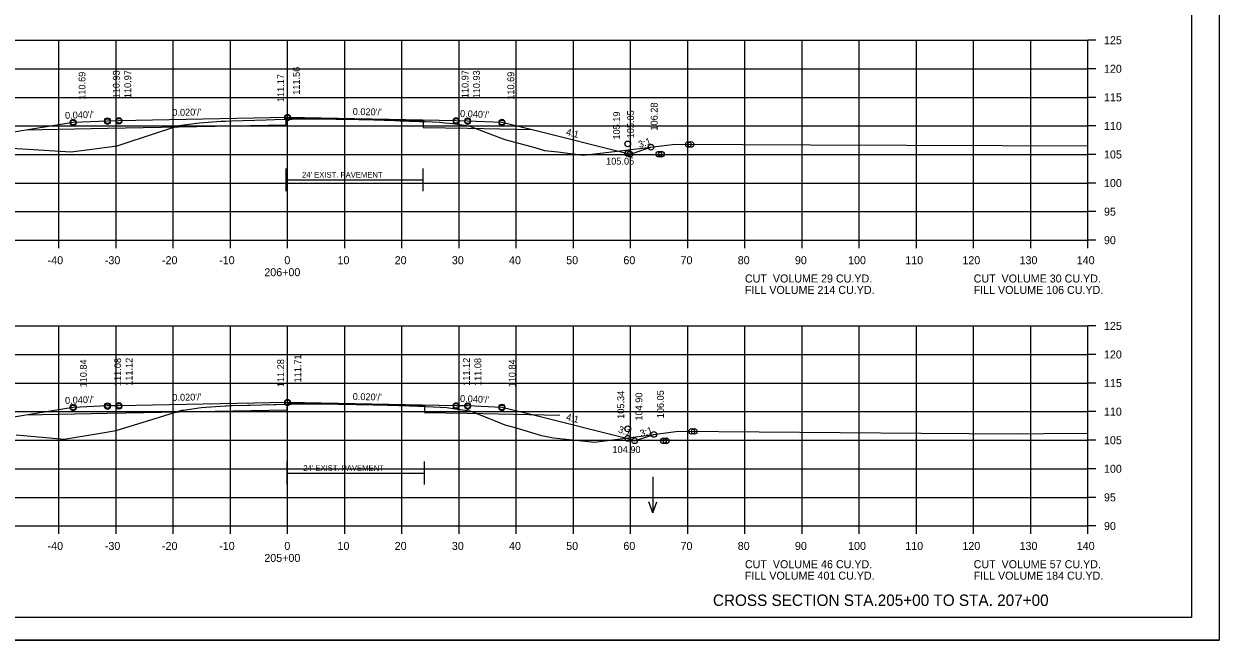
# Model space of a CAD drawing. Extents: x 1175611 to 1176402, y -433344 to -416213.
# Drawn here: x 1175734.9 to 1175943.9, y -425023.4 to -424915.5 of the extents above; entities that cross this region are included whole.
import ezdxf

# ---------------------------------------------------------------- set-up
doc = ezdxf.new("R2010")
doc.units = 0
for name, color, linetype in [('Default', 7, 'Continuous'), ('R_Alt Surface', 7, 'Continuous'), ('R_Axis', 7, 'Continuous'), ('R_Axis Annot', 7, 'Continuous'), ('R_Border', 7, 'Continuous'), ('R_Draft', 7, 'Continuous'), ('R_Exist Surface', 7, 'Continuous'), ('R_Fin Surface', 7, 'Continuous'), ('R_Grid', 7, 'Continuous'), ('R_No Plot', 7, 'Continuous'), ('R_Water Annot', 7, 'Continuous'), ('R_Xsect Elev', 7, 'Continuous'), ('R_Xsect Slope', 7, 'Continuous')]:
    doc.layers.add(name, color=color, linetype=linetype)

msp = doc.modelspace()

# ---------------------------------------------------------------- linework, layer by layer
at = {"layer": 'R_Alt Surface'}
for p, q in [((1175780.7, -424942.81), (1175804.7, -424942.81)), ((1175780.91, -424994.12), (1175804.91, -424994.12))]:
    msp.add_line(p, q, dxfattribs=at)
for points in [[(1175735.2, -424934.07), (1175749.47, -424933.78), (1175780.7, -424933.16), (1175780.7, -424931.98), (1175780.97, -424931.98), (1175804.7, -424932.46), (1175804.7, -424933.63), (1175812.47, -424933.78), (1175823.75, -424934.01)], [(1175780.7, -424944.81), (1175780.7, -424940.81)], [(1175804.7, -424944.81), (1175804.7, -424940.81)], [(1175735.2, -424983.94), (1175749.47, -424983.65), (1175780.91, -424983.03), (1175780.97, -424981.86), (1175780.97, -424981.86), (1175804.91, -424982.34), (1175804.91, -424983.5), (1175812.47, -424983.65), (1175828.57, -424983.98)], [(1175780.91, -424996.12), (1175780.91, -424992.12)], [(1175804.91, -424996.12), (1175804.91, -424992.12)]]:
    msp.add_lwpolyline(points, dxfattribs=at)
at = {"layer": 'R_Axis'}
for p, q in [((1175920.97, -424953.37), (1175920.97, -424918.37)), ((1175922.37, -424918.37), (1175920.97, -424918.37)), ((1175922.37, -424923.37), (1175920.97, -424923.37)), ((1175922.37, -424928.37), (1175920.97, -424928.37)), ((1175922.37, -424933.37), (1175920.97, -424933.37)), ((1175922.37, -424938.37), (1175920.97, -424938.37)), ((1175922.37, -424943.37), (1175920.97, -424943.37)), ((1175922.37, -424948.37), (1175920.97, -424948.37)), ((1175640.97, -424953.37), (1175920.97, -424953.37)), ((1175740.97, -424954.77), (1175740.97, -424953.37)), ((1175750.97, -424954.77), (1175750.97, -424953.37)), ((1175760.97, -424954.77), (1175760.97, -424953.37)), ((1175770.97, -424954.77), (1175770.97, -424953.37)), ((1175780.97, -424954.77), (1175780.97, -424953.37)), ((1175790.97, -424954.77), (1175790.97, -424953.37)), ((1175800.97, -424954.77), (1175800.97, -424953.37)), ((1175810.97, -424954.77), (1175810.97, -424953.37)), ((1175820.97, -424954.77), (1175820.97, -424953.37)), ((1175830.97, -424954.77), (1175830.97, -424953.37)), ((1175840.97, -424954.77), (1175840.97, -424953.37)), ((1175850.97, -424954.77), (1175850.97, -424953.37)), ((1175860.97, -424954.77), (1175860.97, -424953.37)), ((1175870.97, -424954.77), (1175870.97, -424953.37)), ((1175880.97, -424954.77), (1175880.97, -424953.37)), ((1175890.97, -424954.77), (1175890.97, -424953.37)), ((1175900.97, -424954.77), (1175900.97, -424953.37)), ((1175910.97, -424954.77), (1175910.97, -424953.37)), ((1175920.97, -424954.77), (1175920.97, -424953.37)), ((1175922.37, -424953.37), (1175920.97, -424953.37)), ((1175920.97, -425003.37), (1175920.97, -424968.37)), ((1175922.37, -424968.37), (1175920.97, -424968.37)), ((1175922.37, -424973.37), (1175920.97, -424973.37)), ((1175922.37, -424978.37), (1175920.97, -424978.37)), ((1175922.37, -424983.37), (1175920.97, -424983.37)), ((1175922.37, -424988.37), (1175920.97, -424988.37)), ((1175922.37, -424993.37), (1175920.97, -424993.37)), ((1175922.37, -424998.37), (1175920.97, -424998.37)), ((1175640.97, -425003.37), (1175920.97, -425003.37)), ((1175740.97, -425004.77), (1175740.97, -425003.37)), ((1175750.97, -425004.77), (1175750.97, -425003.37)), ((1175760.97, -425004.77), (1175760.97, -425003.37)), ((1175770.97, -425004.77), (1175770.97, -425003.37)), ((1175780.97, -425004.77), (1175780.97, -425003.37)), ((1175790.97, -425004.77), (1175790.97, -425003.37)), ((1175800.97, -425004.77), (1175800.97, -425003.37)), ((1175810.97, -425004.77), (1175810.97, -425003.37)), ((1175820.97, -425004.77), (1175820.97, -425003.37)), ((1175830.97, -425004.77), (1175830.97, -425003.37)), ((1175840.97, -425004.77), (1175840.97, -425003.37)), ((1175850.97, -425004.77), (1175850.97, -425003.37)), ((1175860.97, -425004.77), (1175860.97, -425003.37)), ((1175870.97, -425004.77), (1175870.97, -425003.37)), ((1175880.97, -425004.77), (1175880.97, -425003.37)), ((1175890.97, -425004.77), (1175890.97, -425003.37)), ((1175900.97, -425004.77), (1175900.97, -425003.37)), ((1175910.97, -425004.77), (1175910.97, -425003.37)), ((1175920.97, -425004.77), (1175920.97, -425003.37)), ((1175922.37, -425003.37), (1175920.97, -425003.37))]:
    msp.add_line(p, q, dxfattribs=at)
at = {"layer": 'R_Border'}
for q in [(1175939.15, -424813.91), (1175622.97, -425019.37)]:
    msp.add_line((1175939.15, -425019.37), q, dxfattribs=at)
at = {"layer": 'R_Exist Surface'}
for points in [[(1175728.05, -424936.95), (1175743.05, -424937.92), (1175745.85, -424937.56), (1175751.19, -424936.85), (1175758.24, -424934.54), (1175762.03, -424933.3), (1175762.82, -424933.18), (1175765.57, -424932.81), (1175769.35, -424932.56), (1175769.97, -424932.51), (1175770.01, -424932.51), (1175770.03, -424932.51), (1175771.21, -424932.47), (1175777.23, -424932.28), (1175778.66, -424932.25), (1175781.45, -424932.18), (1175781.77, -424932.18), (1175782.98, -424932.15), (1175784.22, -424932.15), (1175788.23, -424932.13), (1175789.42, -424932.16), (1175793.43, -424932.25), (1175794.21, -424932.27), (1175799.75, -424932.43), (1175800.67, -424932.46), (1175804.07, -424932.58), (1175805.05, -424932.62), (1175806.24, -424932.68), (1175807.57, -424932.74), (1175808.47, -424932.8), (1175809.22, -424932.89), (1175810.29, -424933.03), (1175812.7, -424933.35), (1175816.37, -424934.78), (1175818.97, -424935.73), (1175824.2, -424937.17), (1175825.9, -424937.66), (1175828.25, -424937.93), (1175832.7, -424938.47), (1175839.16, -424937.74), (1175848.75, -424936.59), (1175872.46, -424936.69), (1175905.97, -424936.8), (1175920.97, -424936.84)], [(1175733.48, -424987.44), (1175741.88, -424988.2), (1175747.93, -424987.17), (1175751, -424986.67), (1175759.48, -424984.07), (1175762.47, -424983.14), (1175762.79, -424983.1), (1175765.84, -424982.67), (1175770.03, -424982.37), (1175770.26, -424982.35), (1175770.32, -424982.35), (1175771, -424982.31), (1175771.29, -424982.31), (1175773.98, -424982.24), (1175774.46, -424982.23), (1175778.58, -424982.13), (1175778.94, -424982.12), (1175781.67, -424982.07), (1175784.85, -424982.01), (1175785.39, -424982.01), (1175789.15, -424982.03), (1175789.85, -424982.04), (1175793.8, -424982.13), (1175794.5, -424982.14), (1175800.42, -424982.28), (1175800.91, -424982.3), (1175805.24, -424982.46), (1175807.68, -424982.61), (1175808.85, -424982.67), (1175810.69, -424982.92), (1175812.91, -424983.24), (1175817.69, -424985.15), (1175818.95, -424985.68), (1175820.57, -424986.11), (1175825.4, -424987.56), (1175827.47, -424987.98), (1175830.8, -424988.3), (1175834.66, -424988.69), (1175843.67, -424987.52), (1175849.28, -424986.8), (1175891.79, -424987.12), (1175908.51, -424987.24), (1175913.3, -424987.22), (1175920.97, -424987.16)]]:
    msp.add_lwpolyline(points, dxfattribs=at)
at = {"layer": 'R_Fin Surface'}
for points in [[(1175711.49, -424936.7), (1175715.96, -424938.19), (1175721.47, -424936.35), (1175735.2, -424934.07), (1175743.47, -424932.69), (1175749.47, -424932.45), (1175751.47, -424932.41), (1175780.97, -424931.82), (1175810.47, -424932.41), (1175812.47, -424932.45), (1175818.47, -424932.69), (1175823.75, -424934.01), (1175840.47, -424938.19), (1175840.87, -424938.32), (1175844.54, -424937.1)], [(1175710.51, -424986.75), (1175715.21, -424988.31), (1175721.47, -424986.23), (1175735.2, -424983.94), (1175743.47, -424982.56), (1175749.47, -424982.32), (1175751.47, -424982.28), (1175780.97, -424981.69), (1175810.47, -424982.28), (1175812.47, -424982.32), (1175818.47, -424982.56), (1175823.75, -424983.88), (1175840.47, -424988.06), (1175841.68, -424988.46), (1175845.03, -424987.35)]]:
    msp.add_lwpolyline(points, dxfattribs=at)
at = {"layer": 'R_Grid'}
for p, q in [((1175640.97, -424918.37), (1175920.97, -424918.37)), ((1175740.97, -424953.37), (1175740.97, -424918.37)), ((1175750.97, -424953.37), (1175750.97, -424918.37)), ((1175760.97, -424953.37), (1175760.97, -424918.37)), ((1175770.97, -424953.37), (1175770.97, -424918.37)), ((1175780.97, -424953.37), (1175780.97, -424918.37)), ((1175790.97, -424953.37), (1175790.97, -424918.37)), ((1175800.97, -424953.37), (1175800.97, -424918.37)), ((1175810.97, -424953.37), (1175810.97, -424918.37)), ((1175820.97, -424953.37), (1175820.97, -424918.37)), ((1175830.97, -424953.37), (1175830.97, -424918.37)), ((1175840.97, -424953.37), (1175840.97, -424918.37)), ((1175850.97, -424953.37), (1175850.97, -424918.37)), ((1175860.97, -424953.37), (1175860.97, -424918.37)), ((1175870.97, -424953.37), (1175870.97, -424918.37)), ((1175880.97, -424953.37), (1175880.97, -424918.37)), ((1175890.97, -424953.37), (1175890.97, -424918.37)), ((1175900.97, -424953.37), (1175900.97, -424918.37)), ((1175910.97, -424953.37), (1175910.97, -424918.37)), ((1175920.97, -424953.37), (1175920.97, -424918.37)), ((1175640.97, -424923.37), (1175920.97, -424923.37)), ((1175640.97, -424928.37), (1175920.97, -424928.37)), ((1175640.97, -424933.37), (1175920.97, -424933.37)), ((1175640.97, -424938.37), (1175920.97, -424938.37)), ((1175640.97, -424943.37), (1175920.97, -424943.37)), ((1175640.97, -424948.37), (1175920.97, -424948.37)), ((1175640.97, -424953.37), (1175920.97, -424953.37)), ((1175640.97, -424968.37), (1175920.97, -424968.37)), ((1175740.97, -425003.37), (1175740.97, -424968.37)), ((1175750.97, -425003.37), (1175750.97, -424968.37)), ((1175760.97, -425003.37), (1175760.97, -424968.37)), ((1175770.97, -425003.37), (1175770.97, -424968.37)), ((1175780.97, -425003.37), (1175780.97, -424968.37)), ((1175790.97, -425003.37), (1175790.97, -424968.37)), ((1175800.97, -425003.37), (1175800.97, -424968.37)), ((1175810.97, -425003.37), (1175810.97, -424968.37)), ((1175820.97, -425003.37), (1175820.97, -424968.37)), ((1175830.97, -425003.37), (1175830.97, -424968.37)), ((1175840.97, -425003.37), (1175840.97, -424968.37)), ((1175850.97, -425003.37), (1175850.97, -424968.37)), ((1175860.97, -425003.37), (1175860.97, -424968.37)), ((1175870.97, -425003.37), (1175870.97, -424968.37)), ((1175880.97, -425003.37), (1175880.97, -424968.37)), ((1175890.97, -425003.37), (1175890.97, -424968.37)), ((1175900.97, -425003.37), (1175900.97, -424968.37)), ((1175910.97, -425003.37), (1175910.97, -424968.37)), ((1175920.97, -425003.37), (1175920.97, -424968.37)), ((1175640.97, -424973.37), (1175920.97, -424973.37)), ((1175640.97, -424978.37), (1175920.97, -424978.37)), ((1175640.97, -424983.37), (1175920.97, -424983.37)), ((1175640.97, -424988.37), (1175920.97, -424988.37)), ((1175640.97, -424993.37), (1175920.97, -424993.37)), ((1175640.97, -424998.37), (1175920.97, -424998.37)), ((1175640.97, -425003.37), (1175920.97, -425003.37))]:
    msp.add_line(p, q, dxfattribs=at)
at = {"layer": 'R_No Plot'}
msp.add_line((1175610.57, -425023.35), (1175943.91, -425023.35), dxfattribs=at)
msp.add_lwpolyline([(1175610.57, -424810.01), (1175943.91, -424810.01), (1175943.91, -425023.35), (1175610.57, -425023.35)], close=True, dxfattribs=at)
for centre in [(1175743.47, -424932.69), (1175743.47, -424932.84), (1175749.47, -424932.45), (1175749.47, -424932.6), (1175751.47, -424932.41), (1175751.47, -424932.56), (1175780.97, -424931.82), (1175780.97, -424931.97), (1175810.47, -424932.41), (1175810.47, -424932.56), (1175812.47, -424932.45), (1175812.47, -424932.6), (1175818.47, -424932.69), (1175818.47, -424932.84), (1175840.47, -424936.51), (1175844.54, -424937.1), (1175851.07, -424936.6), (1175851.53, -424936.6), (1175840.47, -424938.19), (1175840.87, -424938.32), (1175845.91, -424938.32), (1175846.37, -424938.32), (1175743.47, -424982.56), (1175743.47, -424982.72), (1175749.47, -424982.32), (1175749.47, -424982.48), (1175751.47, -424982.28), (1175751.47, -424982.44), (1175780.97, -424981.69), (1175780.97, -424981.85), (1175810.47, -424982.28), (1175810.47, -424982.44), (1175812.47, -424982.32), (1175812.47, -424982.48), (1175818.47, -424982.56), (1175818.47, -424982.72), (1175840.47, -424986.38), (1175845.03, -424987.35), (1175851.67, -424986.82), (1175852.12, -424986.82), (1175840.47, -424988.06), (1175841.68, -424988.46), (1175846.72, -424988.47), (1175847.18, -424988.46)]:
    msp.add_circle(centre, 0.5, dxfattribs=at)
at = {"layer": 'R_Water Annot'}
for p, q in [((1175844.88, -424994.79), (1175844.88, -425001.07)), ((1175844.88, -425001.07), (1175844.18, -424999.15)), ((1175844.88, -425001.07), (1175845.58, -424999.15))]:
    msp.add_line(p, q, dxfattribs=at)

# ---------------------------------------------------------------- texts
at = {"layer": 'Default'}
for s, p in [('CUT  VOLUME 29 CU.YD.', (1175860.97, -424960.77)), ('CUT  VOLUME 30 CU.YD.', (1175900.97, -424960.77)), ('FILL VOLUME 214 CU.YD.', (1175860.97, -424962.77)), ('FILL VOLUME 106 CU.YD.', (1175900.97, -424962.77)), ('CUT  VOLUME 46 CU.YD.', (1175860.97, -425010.77)), ('CUT  VOLUME 57 CU.YD.', (1175900.97, -425010.77)), ('FILL VOLUME 401 CU.YD.', (1175860.97, -425012.77)), ('FILL VOLUME 184 CU.YD.', (1175900.97, -425012.77))]:
    msp.add_text(s, height=1.4, dxfattribs=at).set_placement(p)
at = {"layer": 'R_Alt Surface'}
for p in [(1175783.51, -424942.42), (1175783.73, -424993.74)]:
    msp.add_text("24' EXIST. PAVEMENT", height=1, dxfattribs=at).set_placement(p)
at = {"layer": 'R_Axis Annot'}
for s, p in [('125', (1175923.77, -424919.07)), ('120', (1175923.77, -424924.07)), ('115', (1175923.77, -424929.07)), ('110', (1175923.77, -424934.07)), ('105', (1175923.77, -424939.07)), ('100', (1175923.77, -424944.07)), ('95', (1175923.77, -424949.07)), ('90', (1175923.77, -424954.07)), ('-40', (1175739.01, -424957.57)), ('-30', (1175749.01, -424957.57)), ('-20', (1175759.01, -424957.57)), ('-10', (1175769.01, -424957.57)), ('0', (1175780.41, -424957.57)), ('10', (1175789.71, -424957.57)), ('20', (1175799.71, -424957.57)), ('30', (1175809.71, -424957.57)), ('40', (1175819.71, -424957.57)), ('50', (1175829.71, -424957.57)), ('60', (1175839.71, -424957.57)), ('70', (1175849.71, -424957.57)), ('80', (1175859.71, -424957.57)), ('90', (1175869.71, -424957.57)), ('100', (1175879.01, -424957.57)), ('110', (1175889.01, -424957.57)), ('120', (1175899.01, -424957.57)), ('130', (1175909.01, -424957.57)), ('140', (1175919.01, -424957.57)), ('206+00', (1175776.91, -424959.67)), ('125', (1175923.77, -424969.07)), ('120', (1175923.77, -424974.07)), ('115', (1175923.77, -424979.07)), ('110', (1175923.77, -424984.07)), ('105', (1175923.77, -424989.07)), ('100', (1175923.77, -424994.07)), ('95', (1175923.77, -424999.07)), ('90', (1175923.77, -425004.07)), ('-40', (1175739.01, -425007.57)), ('-30', (1175749.01, -425007.57)), ('-20', (1175759.01, -425007.57)), ('-10', (1175769.01, -425007.57)), ('0', (1175780.41, -425007.57)), ('10', (1175789.71, -425007.57)), ('20', (1175799.71, -425007.57)), ('30', (1175809.71, -425007.57)), ('40', (1175819.71, -425007.57)), ('50', (1175829.71, -425007.57)), ('60', (1175839.71, -425007.57)), ('70', (1175849.71, -425007.57)), ('80', (1175859.71, -425007.57)), ('90', (1175869.71, -425007.57)), ('100', (1175879.01, -425007.57)), ('110', (1175889.01, -425007.57)), ('120', (1175899.01, -425007.57)), ('130', (1175909.01, -425007.57)), ('140', (1175919.01, -425007.57)), ('205+00', (1175776.91, -425009.67))]:
    msp.add_text(s, height=1.4, dxfattribs=at).set_placement(p)
at = {"layer": 'R_Draft'}
msp.add_text('CROSS SECTION STA.205+00 TO STA. 207+00', height=2, dxfattribs=at).set_placement((1175855.37, -425017.37))
at = {"layer": 'R_Xsect Elev'}
for s, p in [('110.69', (1175745.62, -424928.79)), ('110.93', (1175751.62, -424928.55)), ('110.97', (1175753.62, -424928.51)), ('111.17', (1175780.37, -424929.2)), ('111.56', (1175783.12, -424927.92)), ('110.97', (1175812.62, -424928.51)), ('110.93', (1175814.62, -424928.55)), ('110.69', (1175820.62, -424928.79)), ('106.28', (1175845.69, -424934.18)), ('105.19', (1175839.12, -424935.76)), ('105.05', (1175841.57, -424935.54)), ('110.84', (1175745.86, -424979.13)), ('111.08', (1175751.86, -424978.89)), ('111.12', (1175753.86, -424978.85)), ('111.28', (1175780.37, -424979.09)), ('111.71', (1175783.36, -424978.26)), ('111.12', (1175812.86, -424978.85)), ('111.08', (1175814.86, -424978.89)), ('110.84', (1175820.86, -424979.13)), ('105.34', (1175839.85, -424984.63)), ('104.90', (1175843.02, -424984.94)), ('106.05', (1175846.79, -424984.53))]:
    msp.add_text(s, height=1.2, rotation=90, dxfattribs=at).set_placement(p)
for s, p in [('105.05', (1175836.69, -424940.14)), ('104.90', (1175837.8, -424990.61))]:
    msp.add_text(s, height=1.2, dxfattribs=at).set_placement(p)
at = {"layer": 'R_Xsect Slope'}
for s, rotation, p in [("0.020'/'", 1.1458, (1175760.83, -424931.62)), ("0.020'/'", 358.8542, (1175792.36, -424931.44)), ("0.040'/'", 357.7094, (1175811.12, -424931.79)), ("0.040'/'", 2.2906, (1175742.07, -424932.14)), ('4:1', 345.9638, (1175829.59, -424934.95)), ('3:1', 18.4349, (1175842.55, -424937.23)), ("0.040'/'", 2.2906, (1175742.07, -424982.02)), ("0.020'/'", 1.1458, (1175760.83, -424981.49)), ("0.020'/'", 358.8542, (1175792.36, -424981.32)), ("0.040'/'", 357.7094, (1175811.12, -424981.67)), ('4:1', 345.9638, (1175829.59, -424984.83)), ('3:1', 341.5651, (1175838.7, -424986.98)), ('3:1', 18.4349, (1175842.82, -424987.81))]:
    msp.add_text(s, height=1.2, rotation=rotation, dxfattribs=at).set_placement(p)

doc.saveas('drawing.dxf')
